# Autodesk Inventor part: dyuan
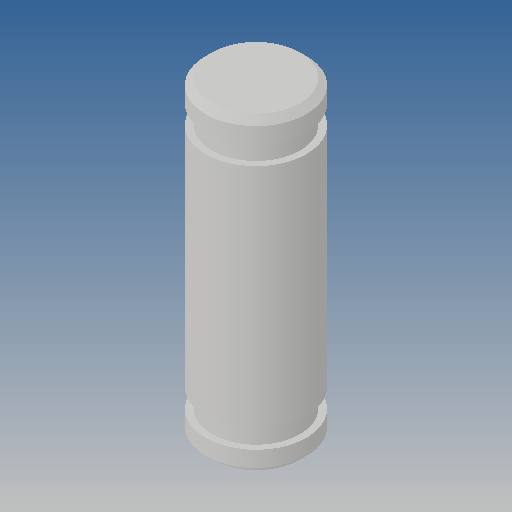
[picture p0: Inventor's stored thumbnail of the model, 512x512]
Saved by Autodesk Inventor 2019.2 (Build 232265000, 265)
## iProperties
Created: 2013-07
Part Number: dyuan
Material: Ogólny
Document SubType Name: Modeling
Designer: CADENGINEERING4
Density: 1 g/cm^3
Appearance: Domyślna
Author: CADENGINEERING4
Revision Number: ÈÎºÎ
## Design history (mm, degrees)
feature "CALC50DX-1-solid1"
node "Bryła1"
